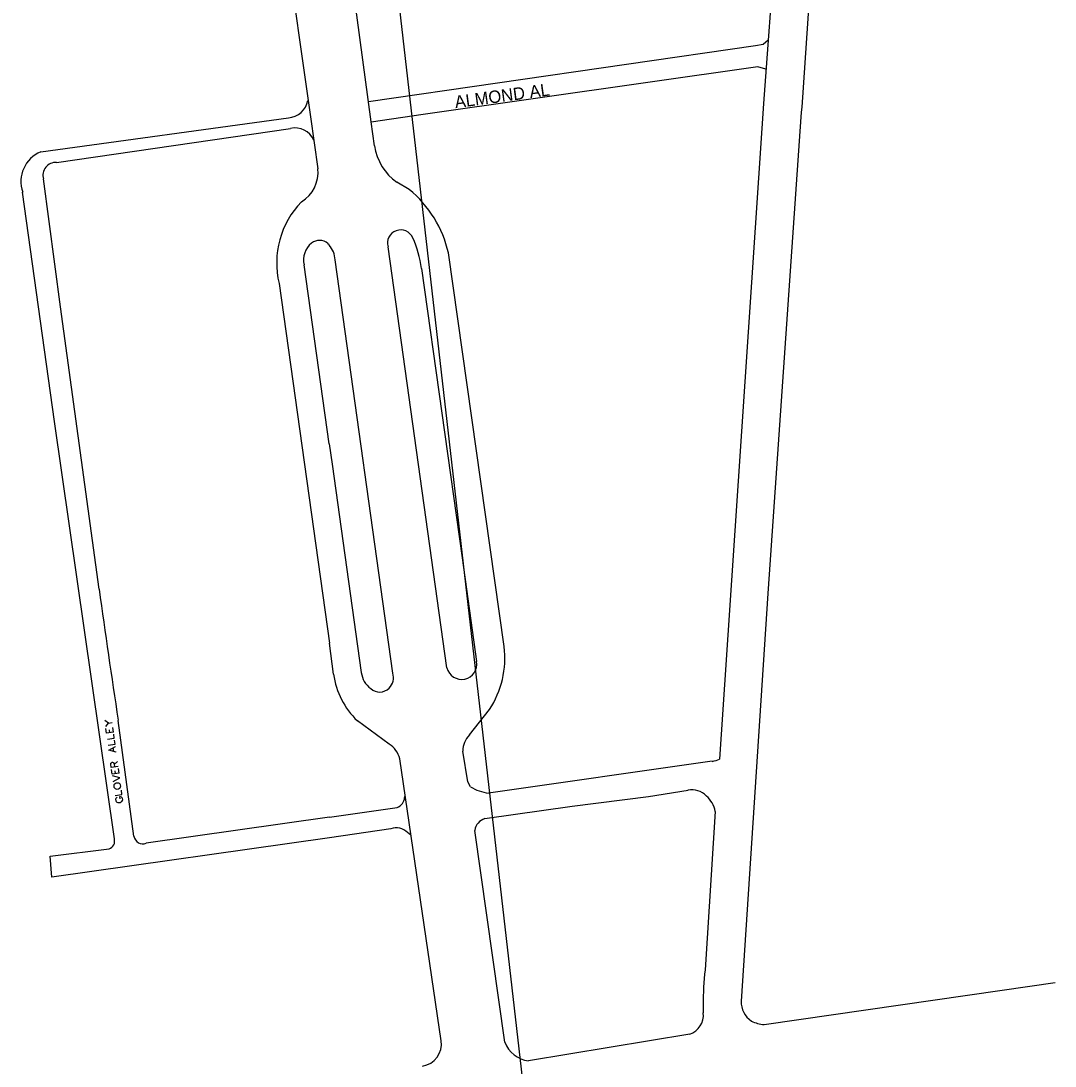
# Model space of a CAD drawing. Extents: x -9648 to 41057, y -12373 to 40276.
# Drawn here: x 9296 to 10132, y -1060 to -215 of the extents above; entities that cross this region are included whole.
import ezdxf

# ---------------------------------------------------------------- set-up
doc = ezdxf.new("R2010")
doc.units = 0
doc.layers.add('SC_Scratch1', color=7, linetype='Continuous')
doc.layers.add('SH_Data', color=7, linetype='Continuous')

msp = doc.modelspace()

# ---------------------------------------------------------------- linework, layer by layer
at = {"layer": 'SC_Scratch1'}
for p, q in [((9447.3, 1145.16), (9704.49, -1100.16)), ((9447.3, 1145.16), (9704.49, -1100.16)), ((9364.01, -781.02), (9364.01, -781.02)), ((9364.64, -785.66), (9364.64, -785.66)), ((9366.99, -782.98), (9366.99, -782.98)), ((9366.99, -782.98), (9366.99, -782.98)), ((9369.88, -782.59), (9369.88, -782.59)), ((9364.87, -787.37), (9364.87, -787.37)), ((9365.39, -791.15), (9365.39, -791.15)), ((9367.74, -788.47), (9367.74, -788.47)), ((9368.05, -790.79), (9368.05, -790.79)), ((9370.42, -786.62), (9370.42, -786.62)), ((9370.94, -790.4), (9370.94, -790.4)), ((9370.94, -790.4), (9370.94, -790.4)), ((9371.13, -791.86), (9371.13, -791.86)), ((9366.05, -796.04), (9366.05, -796.04)), ((9366.72, -800.92), (9366.72, -800.92)), ((9371.6, -795.28), (9371.6, -795.28)), ((9371.8, -796.75), (9371.8, -796.75)), ((9372.27, -800.16), (9372.27, -800.16)), ((9372.5, -801.87), (9372.5, -801.87)), ((9367.26, -804.95), (9367.26, -804.95)), ((9370.73, -802.98), (9370.73, -802.98)), ((9371.12, -805.91), (9371.12, -805.91)), ((9373.13, -806.51), (9373.13, -806.51)), ((9368.81, -816.3), (9368.81, -816.3)), ((9368.91, -815.42), (9368.91, -815.42)), ((9369.15, -818.86), (9369.15, -818.86)), ((9369.2, -815), (9369.2, -815)), ((9369.61, -814.7), (9369.61, -814.7)), ((9370.16, -814.62), (9370.16, -814.62)), ((9370.75, -814.79), (9370.75, -814.79)), ((9371.02, -815.13), (9371.02, -815.13)), ((9371.47, -815.94), (9371.47, -815.94)), ((9371.55, -816.55), (9371.55, -816.55)), ((9371.82, -818.5), (9371.82, -818.5)), ((9374.16, -814.08), (9374.16, -814.08)), ((9374.7, -818.11), (9374.7, -818.11)), ((9369.39, -820.57), (9369.39, -820.57)), ((9369.9, -824.36), (9369.9, -824.36)), ((9370.07, -825.58), (9370.07, -825.58)), ((9372.25, -821.68), (9372.25, -821.68)), ((9372.56, -824), (9372.56, -824)), ((9374.94, -819.82), (9374.94, -819.82)), ((9375.45, -823.6), (9375.45, -823.6)), ((9375.45, -823.6), (9375.45, -823.6)), ((9375.93, -827.14), (9375.93, -827.14)), ((9370.7, -830.22), (9370.7, -830.22)), ((9371.16, -833.63), (9371.16, -833.63)), ((9371.3, -832.99), (9371.3, -832.99)), ((9371.31, -834.74), (9371.31, -834.74)), ((9371.31, -834.74), (9371.31, -834.74)), ((9371.62, -835.31), (9371.62, -835.31)), ((9371.79, -832.43), (9371.79, -832.43)), ((9372.26, -835.85), (9372.26, -835.85)), ((9372.3, -831.99), (9372.3, -831.99)), ((9372.84, -836.02), (9372.84, -836.02)), ((9373.04, -831.64), (9373.04, -831.64)), ((9373.67, -836.28), (9373.67, -836.28)), ((9374.37, -831.46), (9374.37, -831.46)), ((9375, -836.1), (9375, -836.1)), ((9375.18, -831.6), (9375.18, -831.6)), ((9375.73, -835.63), (9375.73, -835.63)), ((9375.78, -831.89), (9375.78, -831.89)), ((9376.25, -835.31), (9376.25, -835.31)), ((9376.41, -832.3), (9376.41, -832.3)), ((9376.71, -832.88), (9376.71, -832.88)), ((9376.72, -834.62), (9376.72, -834.62)), ((9376.86, -833.98), (9376.86, -833.98)), ((9372.22, -841.45), (9372.22, -841.45)), ((9372.66, -844.62), (9372.66, -844.62)), ((9372.8, -843.98), (9372.8, -843.98)), ((9373.29, -843.42), (9373.29, -843.42)), ((9373.79, -842.98), (9373.79, -842.98)), ((9375.9, -842.69), (9375.9, -842.69)), ((9376.1, -844.15), (9376.1, -844.15)), ((9376.68, -842.58), (9376.68, -842.58)), ((9377.28, -842.88), (9377.28, -842.88)), ((9377.31, -837.28), (9377.31, -837.28)), ((9377.77, -840.7), (9377.77, -840.7)), ((9377.9, -843.29), (9377.9, -843.29)), ((9378.21, -843.87), (9378.21, -843.87)), ((9372.82, -845.84), (9372.82, -845.84)), ((9373.11, -846.3), (9373.11, -846.3)), ((9373.75, -846.84), (9373.75, -846.84)), ((9374.35, -847.13), (9374.35, -847.13)), ((9375.16, -847.27), (9375.16, -847.27)), ((9376.49, -847.08), (9376.49, -847.08)), ((9377.24, -846.74), (9377.24, -846.74)), ((9377.74, -846.29), (9377.74, -846.29)), ((9378.22, -845.61), (9378.22, -845.61)), ((9378.37, -845.09), (9378.37, -845.09))]:
    msp.add_line(p, q, dxfattribs=at)
for points in [[(9364.64, -785.66), (9366.99, -782.98), (9364.01, -781.02)], [(9364.64, -785.66), (9366.99, -782.98), (9364.01, -781.02)], [(9366.99, -782.98), (9369.88, -782.59)], [(9366.99, -782.98), (9369.88, -782.59)], [(9370.94, -790.4), (9365.39, -791.15), (9364.87, -787.37)], [(9370.94, -790.4), (9365.39, -791.15), (9364.87, -787.37)], [(9366.05, -796.04), (9371.6, -795.28), (9371.13, -791.86)], [(9366.05, -796.04), (9371.6, -795.28), (9371.13, -791.86)], [(9368.05, -790.79), (9367.74, -788.47)], [(9368.05, -790.79), (9367.74, -788.47)], [(9370.94, -790.4), (9370.42, -786.62)], [(9370.94, -790.4), (9370.42, -786.62)], [(9366.72, -800.92), (9372.27, -800.16), (9371.8, -796.75)], [(9366.72, -800.92), (9372.27, -800.16), (9371.8, -796.75)], [(9373.13, -806.51), (9367.26, -804.95), (9372.5, -801.87)], [(9373.13, -806.51), (9367.26, -804.95), (9372.5, -801.87)], [(9371.12, -805.91), (9370.73, -802.98)], [(9371.12, -805.91), (9370.73, -802.98)], [(9374.7, -818.11), (9369.15, -818.86), (9368.81, -816.3), (9368.91, -815.42), (9369.2, -815), (9369.61, -814.7), (9370.16, -814.62), (9370.75, -814.79), (9371.02, -815.13), (9371.47, -815.94), (9371.82, -818.5)], [(9374.7, -818.11), (9369.15, -818.86), (9368.81, -816.3), (9368.91, -815.42), (9369.2, -815), (9369.61, -814.7), (9370.16, -814.62), (9370.75, -814.79), (9371.02, -815.13), (9371.47, -815.94), (9371.82, -818.5)], [(9371.55, -816.55), (9374.16, -814.08)], [(9371.55, -816.55), (9374.16, -814.08)], [(9375.45, -823.6), (9369.9, -824.36), (9369.39, -820.57)], [(9375.45, -823.6), (9369.9, -824.36), (9369.39, -820.57)], [(9370.7, -830.22), (9375.93, -827.14), (9370.07, -825.58)], [(9370.7, -830.22), (9375.93, -827.14), (9370.07, -825.58)], [(9372.56, -824), (9372.25, -821.68)], [(9372.56, -824), (9372.25, -821.68)], [(9375.45, -823.6), (9374.94, -819.82)], [(9375.45, -823.6), (9374.94, -819.82)], [(9371.31, -834.74), (9371.62, -835.31), (9372.26, -835.85), (9372.84, -836.02), (9373.67, -836.28), (9375, -836.1), (9375.73, -835.63), (9376.25, -835.31), (9376.72, -834.62), (9376.86, -833.98), (9376.71, -832.88), (9376.41, -832.3), (9375.78, -831.89), (9375.18, -831.6), (9374.37, -831.46), (9373.04, -831.64), (9372.3, -831.99), (9371.79, -832.43), (9371.3, -832.99), (9371.16, -833.63), (9371.31, -834.74)], [(9371.31, -834.74), (9371.62, -835.31), (9372.26, -835.85), (9372.84, -836.02), (9373.67, -836.28), (9375, -836.1), (9375.73, -835.63), (9376.25, -835.31), (9376.72, -834.62), (9376.86, -833.98), (9376.71, -832.88), (9376.41, -832.3), (9375.78, -831.89), (9375.18, -831.6), (9374.37, -831.46), (9373.04, -831.64), (9372.3, -831.99), (9371.79, -832.43), (9371.3, -832.99), (9371.16, -833.63), (9371.31, -834.74)], [(9372.22, -841.45), (9377.77, -840.7), (9377.31, -837.28)], [(9372.22, -841.45), (9377.77, -840.7), (9377.31, -837.28)], [(9373.79, -842.98), (9373.29, -843.42), (9372.8, -843.98), (9372.66, -844.62), (9372.82, -845.84), (9373.11, -846.3), (9373.75, -846.84), (9374.35, -847.13), (9375.16, -847.27), (9376.49, -847.08), (9377.24, -846.74), (9377.74, -846.29), (9378.22, -845.61), (9378.37, -845.09), (9378.21, -843.87), (9377.9, -843.29), (9377.28, -842.88), (9376.68, -842.58), (9375.9, -842.69), (9376.1, -844.15)], [(9373.79, -842.98), (9373.29, -843.42), (9372.8, -843.98), (9372.66, -844.62), (9372.82, -845.84), (9373.11, -846.3), (9373.75, -846.84), (9374.35, -847.13), (9375.16, -847.27), (9376.49, -847.08), (9377.24, -846.74), (9377.74, -846.29), (9378.22, -845.61), (9378.37, -845.09), (9378.21, -843.87), (9377.9, -843.29), (9377.28, -842.88), (9376.68, -842.58), (9375.9, -842.69), (9376.1, -844.15)]]:
    msp.add_lwpolyline(points, dxfattribs=at)
at = {"layer": 'SH_Data'}
for p, q in [((9312.12, -321.22), (9512.31, -293.7)), ((9324.93, -329.81), (9513.91, -302.3)), ((9609.94, -351.65), (9599.94, -345.86)), ((9544.17, -395.29), (9545.17, -396.29)), ((9640.36, -738.23), (9592.77, -398.06)), ((9686.55, -721.21), (9641.57, -403.03)), ((9545.26, -557.28), (9524.98, -412.5)), ((9596.56, -742.66), (9549.97, -408.48)), ((9619.78, -415.44), (9652.71, -649.43)), ((9504.78, -427.71), (9545.35, -718.49)), ((9652.71, -649.43), (9664.36, -733.22)), ((9548.76, -743.48), (9545.35, -718.49)), ((9658.59, -792.62), (9674.78, -772.01)), ((9387.44, -874.38), (9374.78, -780.78)), ((9593.59, -800.06), (9567.98, -781.08)), ((9635.73, -1039.84), (9602.2, -811.85)), ((9854.8, -813.91), (9674.02, -839.61)), ((9606.22, -843.05), (9606.51, -841.15)), ((9545.43, -859.09), (9600.02, -851.26)), ((9545.43, -859.09), (9397.44, -880.17)), ((9857.11, -854.38), (9848.9, -982.32)), ((9595.03, -868.46), (9545.44, -875.69)), ((9687.13, -1040.81), (9662.78, -869.7)), ((9611.28, -873.53), (9608.63, -871.45)), ((9847.51, -1010.72), (9847.52, -1017.32)), ((9836.53, -1034.52), (9706.34, -1056))]:
    msp.add_line(p, q, dxfattribs=at)
for points in [[(9941.39, -73.87), (9927, -285.17), (9926.71, -289.27), (9899.53, -678.29), (9878.11, -1007.7)], [(9910.2, -91.88), (9897.69, -260.49), (9896.14, -282.33), (9860.72, -812.04)], [(9581.92, -316.47), (9579.19, -296.92), (9558.43, -142.48)], [(9509.43, -147.11), (9530.11, -293.1), (9536.13, -334.89)], [(9899.88, -230.93), (9895.78, -234.52), (9889.62, -235.58), (9577.03, -280.91)], [(9898.13, -254.58), (9891.49, -252.49), (9621.21, -291.14), (9579.25, -297.37)], [(9359.32, -674.82), (9328.2, -446.61), (9314.34, -343.22)], [(9371.64, -876.58), (9323.25, -539.21), (9297.54, -353.82)], [(9545.26, -557.28), (9547.57, -573.59), (9571.16, -742.07)], [(9659.41, -834.42), (9657.21, -830.42), (9653.2, -805.62)], [(9671.01, -860.2), (9741.57, -850.18), (9803.12, -842.41), (9835.15, -837.27)], [(9545.44, -875.69), (9321.06, -907.61), (9319.64, -890.61), (9367.44, -884.59)], [(9896.72, -1026.69), (10089.11, -998.78), (10131.76, -992.71)]]:
    msp.add_lwpolyline(points, dxfattribs=at)
for centre, radius, start, end in [((9511.32, -276.92), 16.81, 273.36618, 350.51018), ((9517.55, -318.72), 16.82, 23.96218, 102.49018), ((9624.44, -310.62), 42.91, 187.82718, 235.19118), ((9322.33, -345.34), 26.19, 112.91818, 198.89518), ((9324.44, -340.31), 10.51, 87.34518, 196.02818), ((9508.36, -337.77), 27.92, 301.01218, 5.92218), ((9549.6, -424.22), 94.39, 12.97418, 50.25518), ((9573.67, -411.01), 70.88, 135.92518, 193.62918), ((9602.96, -395), 10.64, 22.94718, 196.71418), ((9541.61, -408.49), 17.11, 128.47818, 193.53518), ((9537.44, -403.56), 10.66, 50.89618, 127.43218), ((9531.2, -409.26), 18.79, 2.35818, 41.97718), ((9533.4, -426.78), 87.12, 7.47518, 24.35718), ((15759.26, 204.8), 6460.1, 187.826183, 188.775183), ((9611.07, -730.49), 76.05, 326.90318, 7.00718), ((9652.29, -735.41), 12.26, 193.30418, 10.29618), ((9589.93, -739.81), 18.91, 186.87818, 233.80818), ((9586.43, -746.5), 10.84, 311.20518, 20.78718), ((9612.15, -734.78), 63.98, 187.81918, 226.34618), ((9585.96, -747.27), 10.61, 227.30918, 315.85118), ((9671.65, -805.66), 18.45, 135.05318, 179.89618), ((9584.47, -815.76), 18.16, 12.41218, 59.82218), ((9847.53, -780.65), 34.05, 282.33318, 292.79618), ((9678.26, -804.53), 35.34, 237.76018, 263.09618), ((9597.09, -842.6), 9.13, 288.69518, 357.18318), ((9838.36, -852.95), 16, 43.44418, 101.59418), ((9836.64, -857.85), 20.75, 9.60918, 50.01918), ((9674.6, -871.63), 11.98, 107.46818, 170.73218), ((9599.35, -881.24), 13.49, 46.51718, 108.66818), ((9365.41, -878.42), 6.49, 288.22818, 16.43718), ((9394.72, -873.33), 7.36, 188.15618, 291.68018), ((10049.59, -1006.33), 202.13, 173.17618, 181.24318), ((9897.25, -1008.18), 19.14, 178.56618, 235.19218), ((9831.05, -1018.91), 16.54, 289.32118, 5.54218), ((9899.95, -993.93), 32.92, 245.54818, 264.37918), ((9617.91, -1042.45), 18.01, 279.05218, 8.35818), ((9709.34, -1032.46), 23.73, 200.60418, 262.72518)]:
    msp.add_arc(centre, radius, start, end, dxfattribs=at)

# ---------------------------------------------------------------- texts
at = {"layer": 'SC_Scratch1'}
msp.add_text('ALMOND AL', height=10, rotation=7.69218, dxfattribs=at).set_placement((9647.3, -286.04))

doc.saveas('drawing.dxf')
